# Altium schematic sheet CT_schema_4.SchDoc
size 578 x 363 mm
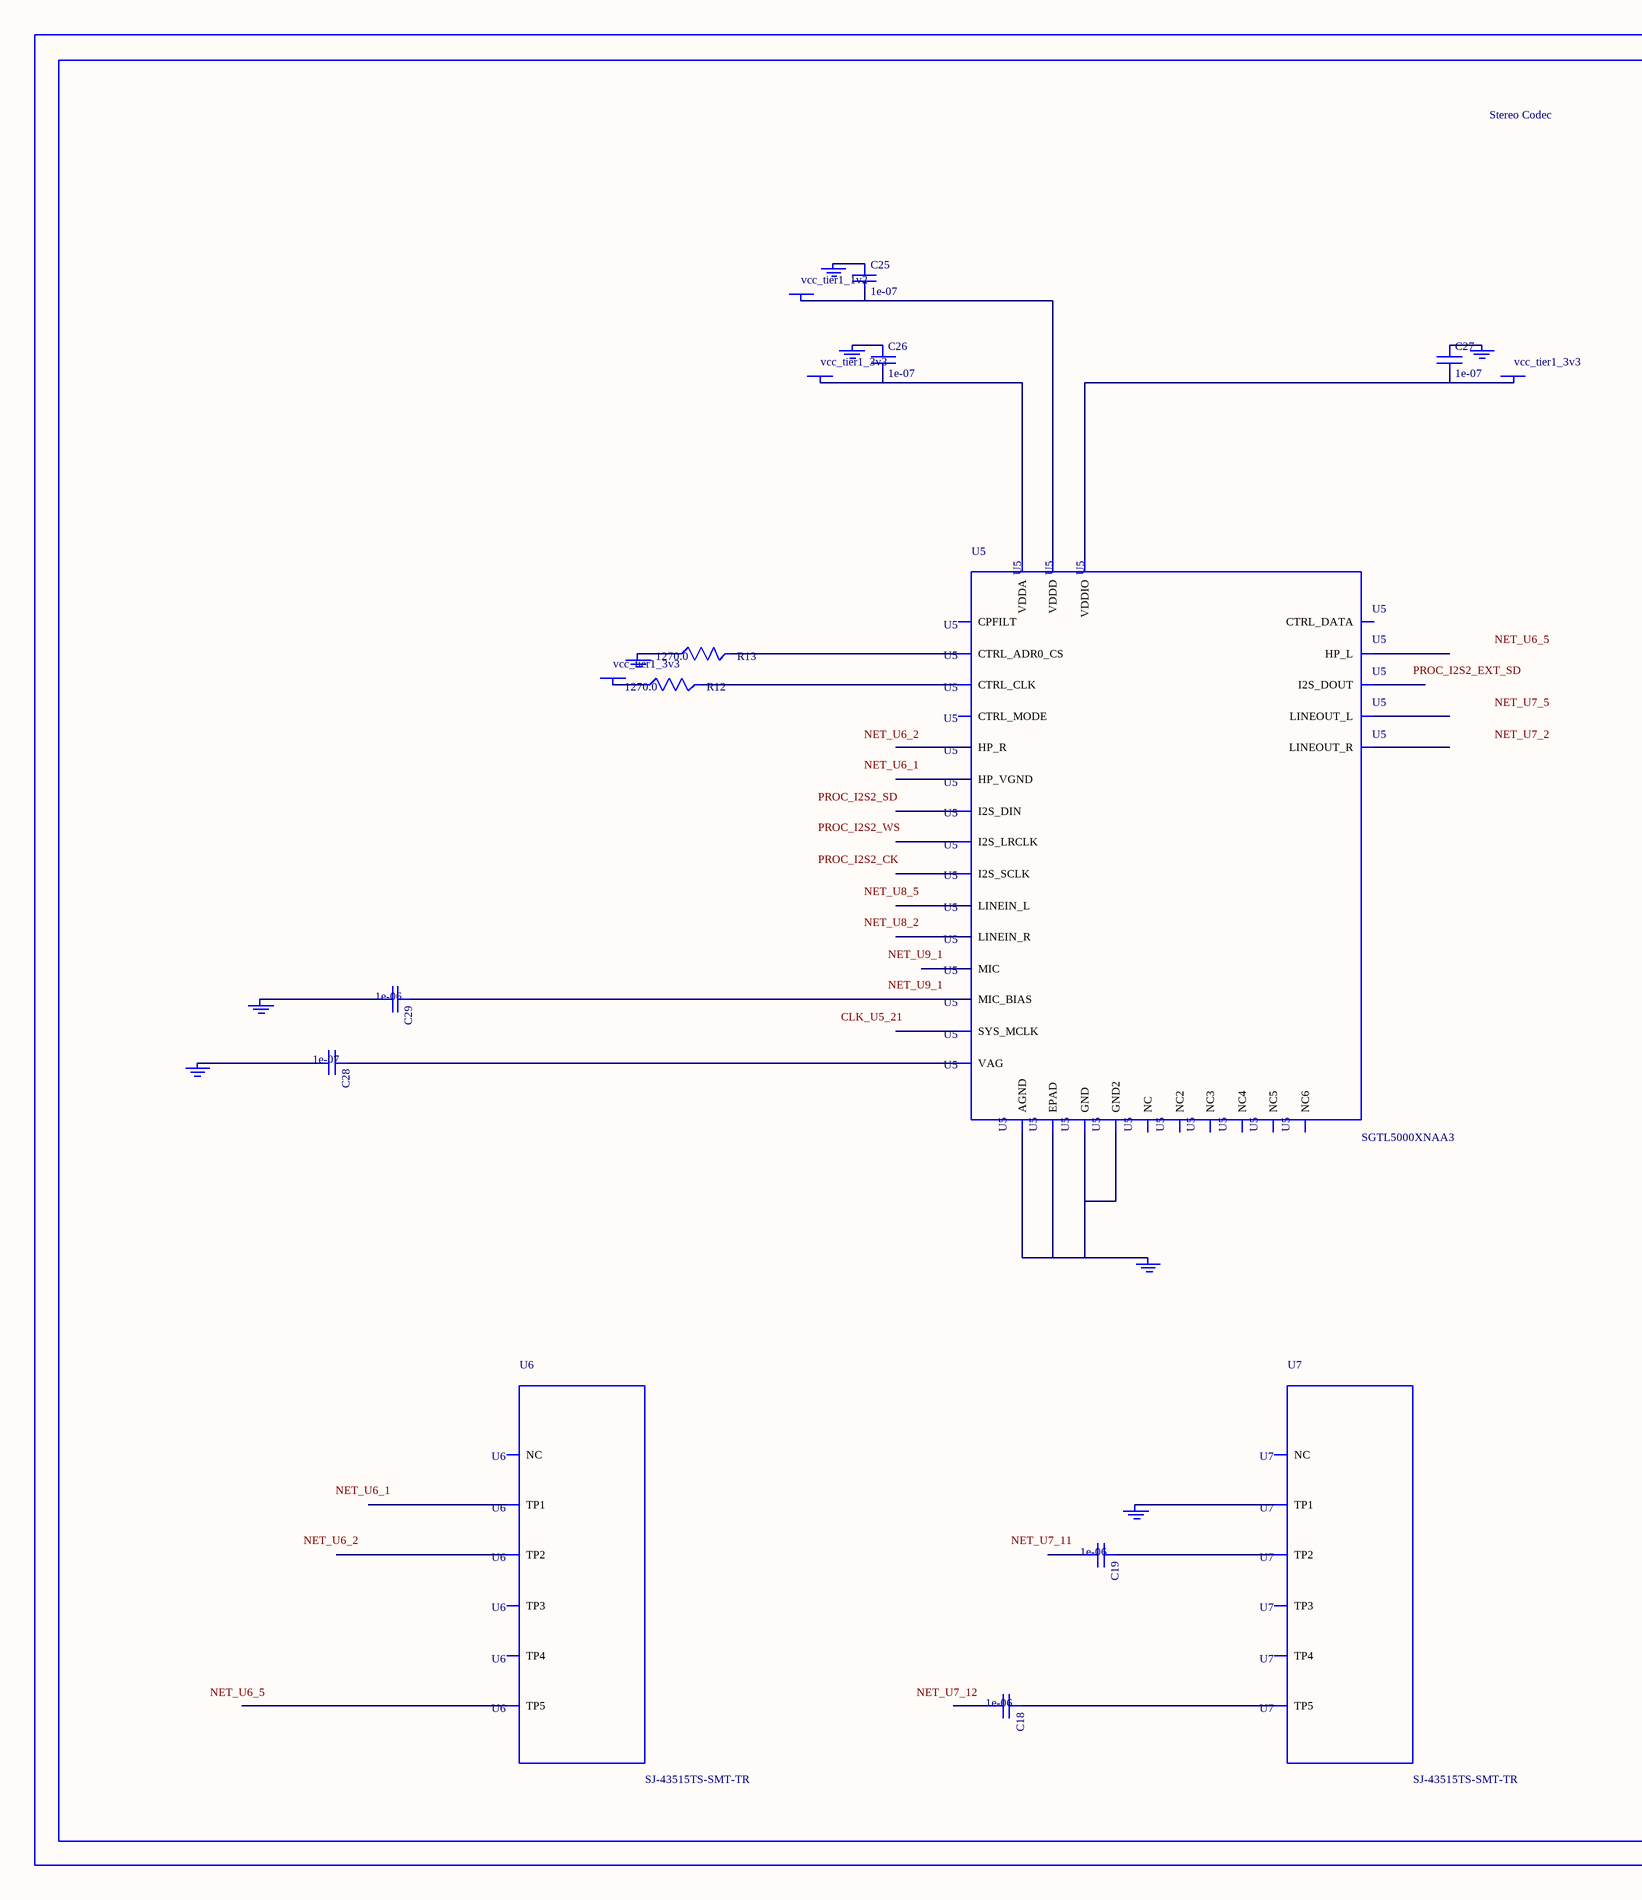
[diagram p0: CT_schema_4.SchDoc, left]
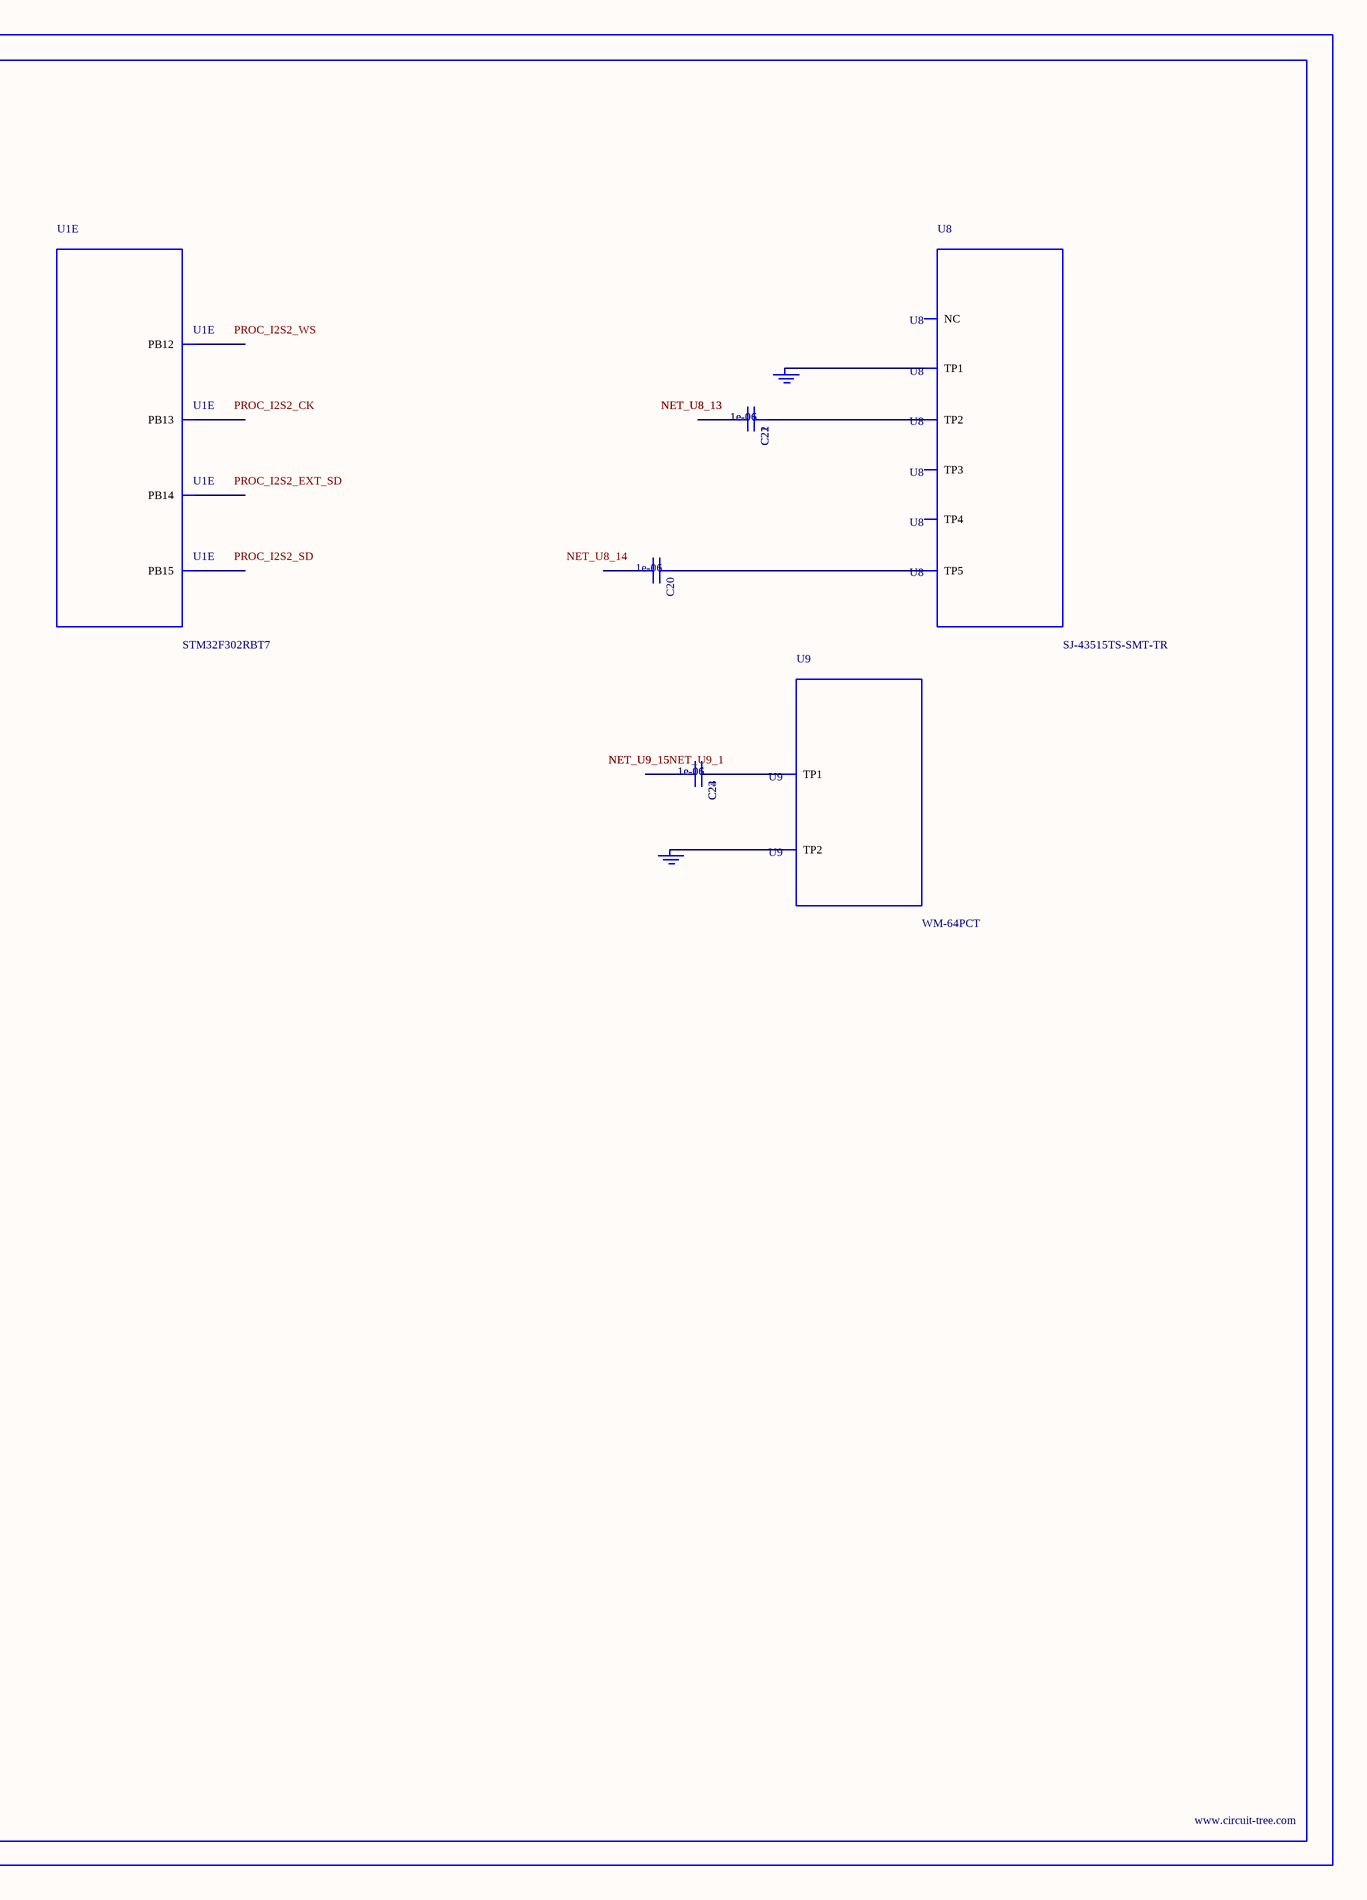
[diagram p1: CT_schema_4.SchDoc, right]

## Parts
BORDER3  (no value)
C18  1e-06  [C0603]
C19  1e-06  [C0603]
C20  1e-06  [C0603]
C21  1e-06  [C0603]
C22  1e-06  [C0603]
C23  1e-06  [C0603]
C24  1e-06  [C0603]
C25  1e-07  [C0402]
C26  1e-07  [C0402]
C27  1e-07  [C0402]
C28  1e-07  [C0402]
C29  1e-06  [C0603]
GND_INSTANCE_3_0  (no value)
GND_INSTANCE_3_1  (no value)
GND_INSTANCE_3_2  (no value)
GND_INSTANCE_3_3  (no value)
GND_INSTANCE_3_4  (no value)
GND_INSTANCE_3_5  (no value)
GND_INSTANCE_3_6  (no value)
GND_INSTANCE_3_7  (no value)
GND_INSTANCE_3_8  (no value)
GND_INSTANCE_3_9  (no value)
GND_INSTANCE_3_10  (no value)
POWER_INSTANCE_3_0  vcc_tier1_3v3
POWER_INSTANCE_3_1  vcc_tier1_3v3
POWER_INSTANCE_3_2  vcc_tier1_3v3
POWER_INSTANCE_3_3  vcc_tier1_1v2
R12  1270.0  [R0603]
R13  1270.0  [R0603]
U1  STM32F302RBT7  [LQFP64]  (part E of 6)
U5  SGTL5000XNAA3  [QFN-32]
U6  SJ-43515TS-SMT-TR  [SJ-43515TS-SMT-TR]
U7  SJ-43515TS-SMT-TR  [SJ-43515TS-SMT-TR]
U8  SJ-43515TS-SMT-TR  [SJ-43515TS-SMT-TR]
U9  WM-64PCT  [WM-64PC]

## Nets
NetC18_1: C18.1 U7.5(TP5)
NetC19_1: C19.1 U7.2(TP2)
NetC20_1: C20.1 U8.5(TP5)
NetC21_1: C21.1 C22.1 U8.2(TP2)
NetC21_2: C21.2 C22.2
NetC23_1: C23.1 C24.1 U9.1(TP1)
NetC23_2: C23.2 C24.2
NetC25_1: C25.1 GND_INSTANCE_3_5.0(GND)
NetC25_2: C25.2 POWER_INSTANCE_3_3.0(PWR) U5.30(VDDD)
NetC26_1: C26.1 GND_INSTANCE_3_1.0(GND)
NetC26_2: C26.2 POWER_INSTANCE_3_0.0(PWR) U5.5(VDDA)
NetC27_1: C27.1 GND_INSTANCE_3_4.0(GND)
NetC27_2: C27.2 POWER_INSTANCE_3_1.0(PWR) U5.20(VDDIO)
NetC28_1: C28.1 U5.10(VAG)
NetC28_2: C28.2 GND_INSTANCE_3_2.0(GND)
NetC29_1: C29.1 U5.16(MIC_BIAS)
NetC29_2: C29.2 GND_INSTANCE_3_3.0(GND)
NetGND_INSTANCE_3_0_0: GND_INSTANCE_3_0.0(GND) U5.1(GND) U5.3(GND2) U5.7(AGND) U5.EXP(EPAD)
NetGND_INSTANCE_3_6_0: GND_INSTANCE_3_6.0(GND) R13.1
NetGND_INSTANCE_3_7_0: GND_INSTANCE_3_7.0(GND) U7.1(TP1)
NetGND_INSTANCE_3_8_0: GND_INSTANCE_3_8.0(GND) GND_INSTANCE_3_9.0(GND) U8.1(TP1)
NetGND_INSTANCE_3_10_0: GND_INSTANCE_3_10.0(GND) U9.2(TP2)
NetPOWER_INSTANCE_3_2_0: POWER_INSTANCE_3_2.0(PWR) R12.1
NetR12_2: R12.2 U5.29(CTRL_CLK)
NetR13_2: R13.2 U5.31(CTRL_ADR0_CS)

Not connected (* = marked no-connect by the designer): C18 2; C19 2; C20 2; U1 33(PB12) 34(PB13) 35(PB14) 36(PB15); U5 2(HP_R) 4(HP_VGND) 6(HP_L) 8(NC) 9(NC2) 11(LINEOUT_R) 12(LINEOUT_L) 13(LINEIN_R) 14(LINEIN_L) 15(MIC) 17(NC3) 18(CPFILT) 19(NC4) 21(SYS_MCLK) 22(NC5) 23(I2S_LRCLK) 24(I2S_SCLK) 25(I2S_DOUT) 26(I2S_DIN) 27(CTRL_DATA) 28(NC6) 32(CTRL_MODE); U6 1(TP1) 2(TP2) 3(TP3) 4(TP4) 5(TP5) 6(NC); U7 3(TP3) 4(TP4) 6(NC); U8 3(TP3) 4(TP4) 6(NC)

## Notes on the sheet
- Labels drawn without touching a wire or pin: CLK_U5_21, NET_U6_1, NET_U6_2, NET_U6_5, NET_U7_2, NET_U7_5, NET_U7_11, NET_U7_12, NET_U8_2, NET_U8_5, NET_U8_14, NET_U9_1, PROC_I2S2_CK, PROC_I2S2_EXT_SD, PROC_I2S2_SD, PROC_I2S2_WS

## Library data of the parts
BORDER3 = BORDER_PAGE3
C18-C24 C29 = C0603C105K3RACTU
C25-C28 = C0402C104K3RACTU
GND_INSTANCE_3_0-GND_INSTANCE_3_10 = GND
POWER_INSTANCE_3_0-POWER_INSTANCE_3_3 = PWR
R12 R13 = RC0603FR-071K27L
